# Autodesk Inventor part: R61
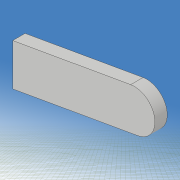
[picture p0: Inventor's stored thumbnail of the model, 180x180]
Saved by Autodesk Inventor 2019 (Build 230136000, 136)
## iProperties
Created: 2021-05
Part Number: R61
Material: 一般
Document SubType Name: Modeling
Designer: kikut
Density: 1 g/cm^3
Appearance: 既定
Mass: 0.0080537 g
Surface Area: 0.40893 cm^2
Volume: 0.0080537 cm^3
Author: kikut
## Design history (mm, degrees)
sketch "スケッチ1"
  geometry: L1 (80, 60)-(-80, 60); L2 (-80, 60)-(-80, -60); L3 (-80, -60)-(80, -60); L4 (80, -60)-(80, 60); L5 (80, 60)-(-80, -60); L6 (-80, 60)-(80, -60); 1 further point
  constraints: 12 end point, 2 midpoint, 2 parallel, 1 horizontal, 1 perpendicular
  dimensions: "d0" = 160 distance of L2.end L3.end; "d1" = 120 distance of L1.end L2.end
extrude "押し出し1" new body sketch "スケッチ1" stored distance "d2" = 0.6; taper "d3" = 0 deg
sketch "スケッチ2"
  geometry: L1 (-140, 0)-(140, 0) reference; L2 (0, -54)-(20, -30); L3 (0, 54)-(20, 30); L4 (0, -3)-(6.514, -3); L5 (6.514, -3)-(16, -6); L6 (16, -6)-(24, -3); L7 (24, -3)-(33.716, -3); L8 (0, 3)-(6.514, 3); L9 (6.514, 3)-(16, 6); L10 (16, 6)-(24, 3); L11 (24, 3)-(33.716, 3); L12 (0, -98)-(0, 98) reference; L13 (-100, -70)-(100, -70); L14 (100, -70)-(100, 70); L15 (100, 70)-(-100, 70); L16 (-100, 70)-(-100, -70); L17 (-100, -70)-(100, 70); L18 (100, -70)-(-100, 70); A1 r 60 centre (54.312, 28.5) between (0, 54) and (0, 3); A2 r 60 centre (54.312, -28.5) between (0, -3) and (0, -54); A3 r 18.111 centre (18, -12) between (20, -30) and (33.716, -3); A4 r 18.111 centre (18, 12) between (33.716, 3) and (20, 30); 1 further point
  constraints: 32 end point, 8 point on circle, 8 symmetric about line, 4 centre point, 3 horizontal, 2 collinear, 2 midpoint, 2 parallel, 1 perpendicular
  dimensions: "d5" = 60 radius of A1; "d6" = 6 distance of L8.start L4.start; "d7" = 108 distance of L3.start L2.start; "d8" = 0 horizontal distance of L3.start L8.start; "d9" = 60 distance of L3.end L2.end; "d10" = 0 horizontal distance of point (0, 0) L3.start; "d11" = 20 horizontal distance of L3.start L3.end; "d12" = 24 distance of A4.centre A3.centre; "d13" = 6 distance of L11.end L7.end; "d14" = 12 distance of L9.end L5.end; "d15" = 16 distance from line of L12 L5.end; "d16" = 24 distance from line of L6.end L12; "d17" = 200 distance of L14.end L15.end; "d18" = 140 distance of L15.end L13.start; "d30" = 18 distance from line of L12 A4.centre
extrude "押し出し2" cut sketch "スケッチ2" stored distance "d19" = 10; taper "d20" = 0 deg
sketch "スケッチ3"
  geometry: L1 (49.705, -17.97)-(33.948, -15.191); L2 (33.948, -15.191)-(34.295, -13.222); L3 (34.295, -13.222)-(50.052, -16); L4 (50.052, -16)-(49.705, -17.97); L5 (49.705, -17.97)-(34.295, -13.222); L6 (33.948, -15.191)-(50.052, -16); L7 (50.052, 16)-(34.295, 13.222); L8 (34.295, 13.222)-(33.948, 15.191); L9 (33.948, 15.191)-(49.705, 17.97); L10 (49.705, 17.97)-(50.052, 16); L11 (50.052, 16)-(33.948, 15.191); L12 (34.295, 13.222)-(49.705, 17.97); L13 (-112, 0)-(112, 0) reference; L14 (0, -84)-(0, 84) reference; 3 further points
  constraints: 24 end point, 4 midpoint, 4 parallel, 2 perpendicular, 2 symmetric about line
  dimensions: "d21" = 2 distance of L3.end L1.start; "d22" = 2 distance of L9.end L7.start; "d23" = 16 distance of L8.end L9.end; "d24" = 42 distance from line of L14 point (42, 15.596); "d26" = 10 deg angle of L7 L13; "d62" = 16 distance from line of L3.end L13
extrude "押し出し3" join sketch "スケッチ3" distance "d27" = 0.6; taper "d28" = 0 deg
fillet "フィレット1" dims "d31" = 2
fillet "フィレット2" dims "d32" = 1
sketch "スケッチ6"
  geometry: L1 (-20, 60)-(80, 60); L2 (80, 60)-(80, -60); L3 (80, -60)-(-20, -60); L4 (-20, -60)-(-20, 60); L5 (-46.168, 0)-(93.832, 0) reference; L6 (0, -84)-(0, 84) reference; L7 (43, 10)-(51, 10); L8 (51, 10)-(51, 20); L9 (51, 20)-(43, 20); L10 (43, 20)-(43, 10); 1 further point
  constraints: 16 end point, 4 parallel, 2 horizontal, 2 perpendicular, 1 other
  dimensions: "d63" = 120 distance of L3.end L1.start; "d64" = 100 distance of L1.start L1.end; "d65" = 20 distance between parallel lines of L6 L4; "d66" = 8 distance of L8.end L9.end; "d73" = 10 distance of L9.end L7.start; "d74" = 10 distance between parallel lines of L7 L5; "d75" = 63 distance between parallel lines of L10 L4
extrude "押し出し4" cut sketch "スケッチ6" stored distance "d70" = 10; taper "d71" = 0 deg
node "ソリッド1"
